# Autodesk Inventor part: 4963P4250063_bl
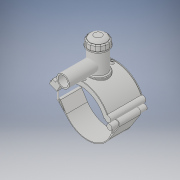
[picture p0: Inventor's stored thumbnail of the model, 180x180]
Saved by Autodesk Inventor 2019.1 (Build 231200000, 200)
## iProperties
Created: 2017-07
Part Number: 4963P4250063_bl
Material: Generic
Document SubType Name: Modeling
Designer: KIM
Density: 1 g/cm^3
Appearance: Default
Author: KIM
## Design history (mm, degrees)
derived "4963P4.ipt"
feature "Solid1::4963P4.ipt" dims "ScaleForDerivedMember" = 10
feature "Solid2::4963P4.ipt" dims "ScaleForDerivedMember" = 10
feature "Solid3::4963P4.ipt" dims "ScaleForDerivedMember" = 10
tag "TaggingFeature1"
body "Solid1"
body "Solid2"
body "Solid3"
other parameters: "B_" = 252 [user parameter], "L_" = 176 [user parameter], "d_t" = 6 [user parameter], "H_2" = 177 [user parameter], "H_1" = 64 [user parameter], "d_1" = 63 [user parameter], "H_" = 175 [user parameter], "d148" = 3.75 [user parameter], "d160" = 3.75 [user parameter], "d169" = 3.75 [user parameter], "d192" = 8 [user parameter], "d2" = 327.6 [user parameter], "d3" = 62.5 [user parameter], "d4" = 176 [user parameter], "d5" = 0 [user parameter], "d6" = 0.1 [user parameter], "d8" = 0 [user parameter], "d19" = 6 [user parameter], "d20" = 6 [user parameter], "d21" = 105.6 [user parameter], "d23" = 0 [user parameter], "d24" = 52.8 [user parameter], "d26" = 0 [user parameter], "d27" = 3 [user parameter], "d28" = 3 [user parameter], "d29" = 3 [user parameter], "d30" = 83.33333 [user parameter], "d31" = 6 [user parameter], "d32" = 0 [user parameter], "d33" = 0 [user parameter], "d34" = 0.6 [user parameter], "d40" = 150.8 [user parameter], "d43" = 0 [user parameter], "d45" = 0 [user parameter], "d47" = 250.6 [user parameter], "d70" = 15 [user parameter], "d72" = 0 [user parameter], "d73" = 6 [user parameter], "d75" = 5 [user parameter], "d76" = 0 [user parameter], "d77" = 12.5 [user parameter], "d78" = 155 [user parameter], "d79" = 15 [user parameter], "d80" = 70.4 [user parameter], "d82" = 5 deg [user parameter], "d84" = 4 [user parameter], "d85" = 14 [user parameter], "d86" = 0 [user parameter], "d87" = 3 [user parameter], "d88" = 0 [user parameter], "d89" = 1 [user parameter], "d90" = 1 [user parameter], "d91" = 140.8 [user parameter], "d92" = 0 [user parameter], "d93" = 0.5 [user parameter], "d94" = 131.57895 [user parameter], "d96" = 295.8 [user parameter], "d97" = 3.52 [user parameter], "d98" = 0 [user parameter], "d102" = 2.5 [user parameter], "d120" = 140 deg [user parameter], "d121" = 24.228 [user parameter], "d122" = 20 deg [user parameter], "d124" = 174 [user parameter], "d126" = 0 [user parameter], "d143" = 257.5 [user parameter], "d145" = 30.76923 [user parameter], "d149" = 3.75 [user parameter], "d150" = 33.84615 [user parameter], "d153" = 176 [user parameter], "d154" = 0 [user parameter], "d156" = 145 [user parameter], "d157" = 160 deg [user parameter], "d159" = 8 [user parameter], "d161" = 3.75 [user parameter], "d162" = 105.6 [user parameter], "d163" = 0 [user parameter], "d164" = 125 [user parameter], "d167" = 25 [user parameter], "d168" = 141.46341 [user parameter], "d170" = 3.75 [user parameter], "d172" = 0 [user parameter], "d173" = 1 [user parameter], "d175" = 125 [user parameter], "d176" = 20 deg [user parameter], "d177" = 17.5 [user parameter], "d180" = 0 [user parameter], "d183" = 16 [user parameter], "d184" = 14 [user parameter], "d185" = 57.2 [user parameter], "d186" = 57.2 [user parameter], "d187" = 145 [user parameter], "d188" = 12 [user parameter], "d189" = 17.5 [user parameter], "d190" = 0 [user parameter], "d191" = 217.5 [user parameter], "d193" = 8 [user parameter], "d194" = 6.16 [user parameter], "d195" = 90 deg [user parameter], "d197" = 0 [user parameter], "d199" = 0 [user parameter], "d202" = 0 [user parameter], "d203" = 177 [user parameter], "d204" = 95 [user parameter], "d206" = 85 [user parameter], "d207" = 132.75 [user parameter], "d208" = 138.06 [user parameter], "d209" = 164.61 [user parameter], "d210" = 86 [user parameter], "d213" = 29.25 [user parameter], "d216" = 0 [user parameter], "d217" = 25 [user parameter], "d218" = 25 [user parameter], "d219" = 5 [user parameter], "d224" = 0 [user parameter], "d225" = 64 [user parameter], "d226" = 63 [user parameter], "d227" = 50.4 [user parameter], "d228" = 175 [user parameter], "d230" = 5 [user parameter]
